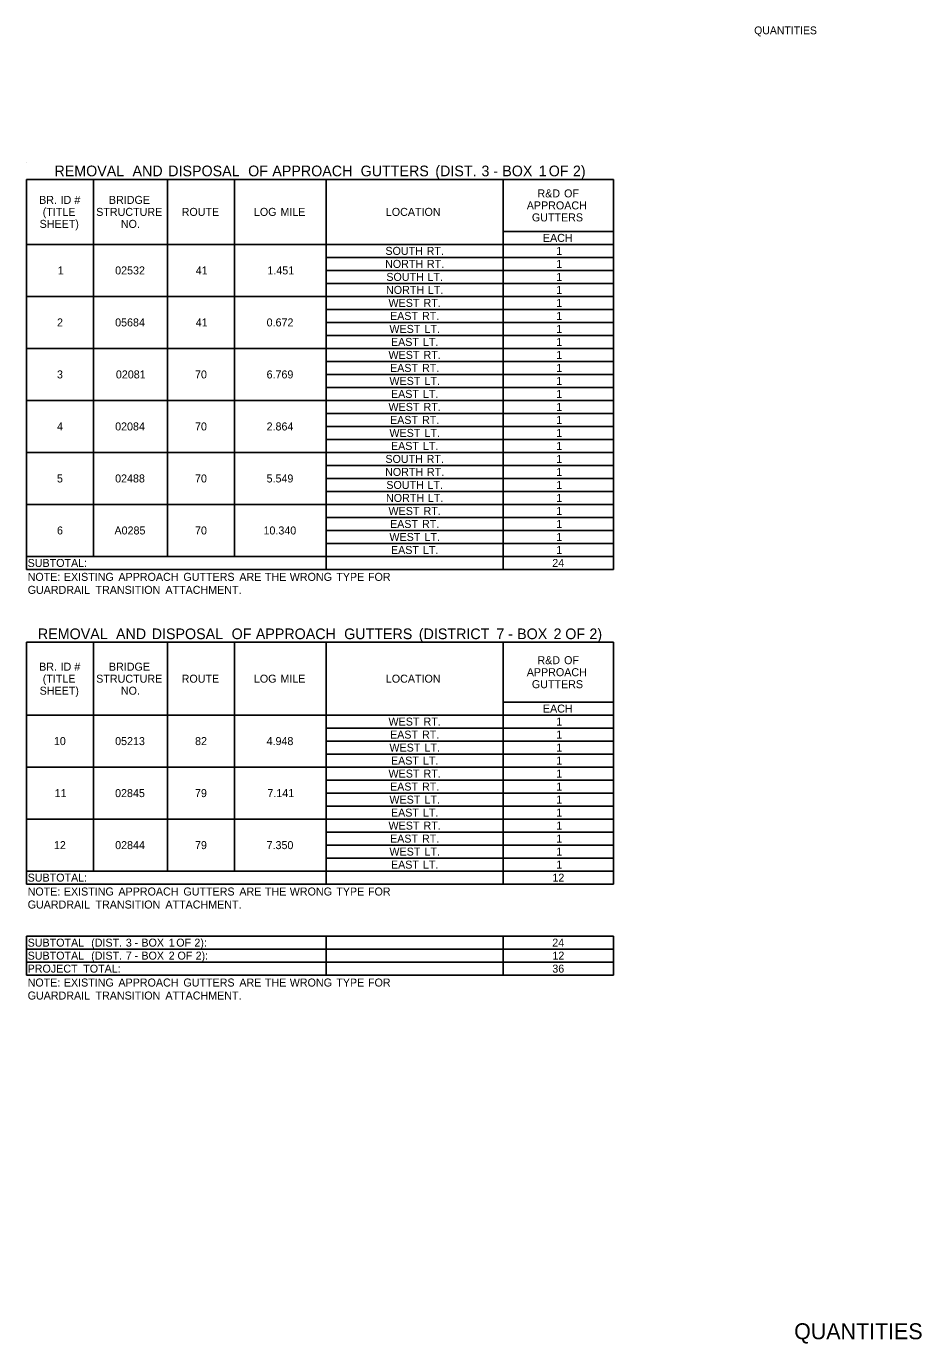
# Model space of a CAD drawing. Extents: x 544478 to 1930787, y -1948294 to 596640.
# Drawn here: x 560318 to 560989, y -1947044 to -1946056 of the extents above; entities that cross this region are included whole.
import ezdxf

# ---------------------------------------------------------------- set-up
doc = ezdxf.new("R2010")
doc.units = 0
for name, color, linetype in [('Default', 7, 'Continuous'), ('R_Border', 7, 'Continuous'), ('R_Border Prem', 7, 'Continuous')]:
    doc.layers.add(name, color=color, linetype=linetype)

msp = doc.modelspace()

# ---------------------------------------------------------------- linework, layer by layer
at = {"layer": 'Default'}
for p, q in [((560317.58, -1946158.53), (560317.58, -1946158.53)), ((560317.58, -1946171.21), (560757.79, -1946171.21)), ((560317.58, -1946463.71), (560317.58, -1946171.21)), ((560367.79, -1946453.96), (560367.79, -1946171.21)), ((560423.37, -1946453.96), (560423.37, -1946171.21)), ((560473.58, -1946453.96), (560473.58, -1946171.21)), ((560542.32, -1946463.71), (560542.32, -1946171.21)), ((560674.92, -1946463.71), (560674.92, -1946171.21)), ((560757.79, -1946463.71), (560757.79, -1946171.21)), ((560674.92, -1946210.21), (560757.79, -1946210.21)), ((560674.92, -1946210.21), (560757.79, -1946210.21)), ((560317.58, -1946219.96), (560757.79, -1946219.96)), ((560542.32, -1946229.71), (560757.79, -1946229.71)), ((560542.32, -1946239.46), (560757.79, -1946239.46)), ((560542.32, -1946249.21), (560757.79, -1946249.21)), ((560317.58, -1946258.96), (560542.32, -1946258.96)), ((560542.32, -1946258.96), (560757.79, -1946258.96)), ((560542.32, -1946268.71), (560757.79, -1946268.71)), ((560542.32, -1946278.46), (560757.79, -1946278.46)), ((560542.32, -1946288.21), (560757.79, -1946288.21)), ((560317.58, -1946297.96), (560757.79, -1946297.96)), ((560542.32, -1946297.96), (560757.79, -1946297.96)), ((560542.32, -1946307.71), (560757.79, -1946307.71)), ((560542.32, -1946317.46), (560757.79, -1946317.46)), ((560542.32, -1946327.21), (560757.79, -1946327.21)), ((560317.58, -1946336.96), (560542.32, -1946336.96)), ((560542.32, -1946336.96), (560757.79, -1946336.96)), ((560674.92, -1946336.96), (560757.79, -1946336.96)), ((560542.32, -1946346.71), (560757.79, -1946346.71)), ((560542.32, -1946356.46), (560757.79, -1946356.46)), ((560542.32, -1946366.21), (560757.79, -1946366.21)), ((560317.58, -1946375.96), (560757.79, -1946375.96)), ((560542.32, -1946375.96), (560757.79, -1946375.96)), ((560542.32, -1946385.71), (560757.79, -1946385.71)), ((560542.32, -1946395.46), (560757.79, -1946395.46)), ((560542.32, -1946405.21), (560757.79, -1946405.21)), ((560317.58, -1946414.96), (560542.32, -1946414.96)), ((560542.32, -1946414.96), (560757.79, -1946414.96)), ((560674.92, -1946414.96), (560757.79, -1946414.96)), ((560542.32, -1946424.71), (560757.79, -1946424.71)), ((560542.32, -1946434.46), (560757.79, -1946434.46)), ((560542.32, -1946444.21), (560757.79, -1946444.21)), ((560317.58, -1946453.96), (560542.32, -1946453.96)), ((560317.58, -1946453.96), (560757.79, -1946453.96)), ((560542.32, -1946463.71), (560542.32, -1946453.96)), ((560317.58, -1946463.71), (560757.79, -1946463.71)), ((560317.58, -1946518.31), (560757.79, -1946518.31)), ((560317.58, -1946699.66), (560317.58, -1946518.31)), ((560367.79, -1946689.91), (560367.79, -1946518.31)), ((560423.37, -1946689.91), (560423.37, -1946518.31)), ((560473.58, -1946689.91), (560473.58, -1946518.31)), ((560542.32, -1946699.66), (560542.32, -1946518.31)), ((560674.92, -1946699.66), (560674.92, -1946518.31)), ((560757.79, -1946699.66), (560757.79, -1946518.31)), ((560674.92, -1946563.16), (560757.79, -1946563.16)), ((560674.92, -1946563.16), (560757.79, -1946563.16)), ((560317.58, -1946572.91), (560757.79, -1946572.91)), ((560317.58, -1946572.91), (560542.32, -1946572.91)), ((560674.92, -1946572.91), (560757.79, -1946572.91)), ((560542.32, -1946582.66), (560757.79, -1946582.66)), ((560542.32, -1946592.41), (560757.79, -1946592.41)), ((560542.32, -1946602.16), (560757.79, -1946602.16)), ((560317.58, -1946611.91), (560757.79, -1946611.91)), ((560542.32, -1946611.91), (560757.79, -1946611.91)), ((560542.32, -1946621.66), (560757.79, -1946621.66)), ((560542.32, -1946631.41), (560757.79, -1946631.41)), ((560542.32, -1946641.16), (560757.79, -1946641.16)), ((560317.58, -1946650.91), (560757.79, -1946650.91)), ((560542.32, -1946650.91), (560757.79, -1946650.91)), ((560542.32, -1946660.66), (560757.79, -1946660.66)), ((560542.32, -1946670.41), (560757.79, -1946670.41)), ((560542.32, -1946680.16), (560757.79, -1946680.16)), ((560317.58, -1946689.91), (560757.79, -1946689.91)), ((560317.58, -1946689.91), (560757.79, -1946689.91)), ((560542.32, -1946699.66), (560542.32, -1946689.91)), ((560317.58, -1946699.66), (560757.79, -1946699.66)), ((560317.58, -1946738.66), (560757.79, -1946738.66)), ((560317.58, -1946738.66), (560757.79, -1946738.66)), ((560317.58, -1946767.91), (560317.58, -1946738.66)), ((560542.32, -1946767.91), (560542.32, -1946738.66)), ((560542.32, -1946767.91), (560542.32, -1946738.66)), ((560674.92, -1946767.91), (560674.92, -1946738.66)), ((560757.79, -1946767.91), (560757.79, -1946738.66)), ((560317.58, -1946748.41), (560757.79, -1946748.41)), ((560317.58, -1946758.16), (560757.79, -1946758.16)), ((560317.58, -1946767.91), (560757.79, -1946767.91))]:
    msp.add_line(p, q, dxfattribs=at)

# ---------------------------------------------------------------- texts
for s, height, p in [('REMOVAL', 8, (560338.62, -1946168.87)), (' AND', 8, (560394.18, -1946168.87)), (' DISPOSAL', 8, (560420.95, -1946168.87)), (' OF', 8, (560480.86, -1946168.87)), (' APPROACH', 8, (560498.97, -1946168.87)), (' GUTTERS', 8, (560565.19, -1946168.87)), (' (DIST.', 8, (560621.16, -1946168.87)), (' 3', 8, (560655.78, -1946168.87)), (' BOX', 8, (560671.36, -1946168.87)), (' 1', 8, (560698.68, -1946168.87)), (' OF', 8, (560706.19, -1946168.87)), (' 2)', 8, (560724.3, -1946168.87)), (' -', 8, (560664.62, -1946168.87)), ('R&D', 6, (560700.69, -1946184.71)), (' OF', 6, (560718.44, -1946184.71)), ('BR.', 6, (560327.16, -1946189.58)), ('(TITLE', 6, (560329.86, -1946198.58)), (' ID', 6, (560341.02, -1946189.58)), (' #', 6, (560351.32, -1946189.58)), ('STRUCTURE', 6, (560369.94, -1946198.58)), ('BRIDGE', 6, (560379.48, -1946189.58)), ('ROUTE', 6, (560434.01, -1946198.58)), ('LOG', 6, (560488.15, -1946198.58)), (' MILE', 6, (560505.81, -1946198.58)), ('LOCATION', 6, (560587.06, -1946198.58)), ('APPROACH', 6, (560692.69, -1946193.71)), ('SHEET)', 6, (560327.53, -1946207.58)), ('NO.', 6, (560388.42, -1946207.58)), ('GUTTERS', 6, (560696.53, -1946202.71)), ('EACH', 6, (560704.8, -1946218.08)), ('SOUTH', 6, (560586.73, -1946227.83)), (' RT.', 6, (560615.4, -1946227.83)), ('1', 6, (560714.8, -1946227.83)), ('NORTH', 6, (560586.5, -1946237.58)), (' RT.', 6, (560615.63, -1946237.58)), ('1', 6, (560714.8, -1946237.58)), ('1', 6, (560341.13, -1946242.46)), ('02532', 6, (560384.15, -1946242.46)), ('41', 6, (560444.58, -1946242.46)), ('1.451', 6, (560498.24, -1946242.46)), ('SOUTH', 6, (560587.43, -1946247.33)), (' LT.', 6, (560616.1, -1946247.33)), ('1', 6, (560714.8, -1946247.33)), ('NORTH', 6, (560587.2, -1946257.08)), (' LT.', 6, (560616.33, -1946257.08)), ('1', 6, (560714.8, -1946257.08)), ('WEST', 6, (560589.04, -1946266.83)), (' RT.', 6, (560613.09, -1946266.83)), ('1', 6, (560714.8, -1946266.83)), ('EAST', 6, (560590.2, -1946276.58)), (' RT.', 6, (560611.93, -1946276.58)), ('1', 6, (560714.8, -1946276.58)), ('2', 6, (560340.58, -1946281.46)), ('05684', 6, (560384.13, -1946281.46)), ('41', 6, (560444.58, -1946281.46)), ('0.672', 6, (560497.69, -1946281.46)), ('WEST', 6, (560589.74, -1946286.33)), (' LT.', 6, (560613.79, -1946286.33)), ('1', 6, (560714.8, -1946286.33)), ('EAST', 6, (560590.9, -1946296.08)), (' LT.', 6, (560612.63, -1946296.08)), ('1', 6, (560714.8, -1946296.08)), ('WEST', 6, (560589.04, -1946305.83)), (' RT.', 6, (560613.09, -1946305.83)), ('1', 6, (560714.8, -1946305.83)), ('EAST', 6, (560590.2, -1946315.58)), (' RT.', 6, (560611.93, -1946315.58)), ('1', 6, (560714.8, -1946315.58)), ('3', 6, (560340.55, -1946320.46)), ('02081', 6, (560384.7, -1946320.46)), ('70', 6, (560444.01, -1946320.46)), ('6.769', 6, (560497.65, -1946320.46)), ('WEST', 6, (560589.74, -1946325.33)), (' LT.', 6, (560613.79, -1946325.33)), ('1', 6, (560714.8, -1946325.33)), ('EAST', 6, (560590.9, -1946335.08)), (' LT.', 6, (560612.63, -1946335.08)), ('1', 6, (560714.8, -1946335.08)), ('WEST', 6, (560589.04, -1946344.83)), (' RT.', 6, (560613.09, -1946344.83)), ('1', 6, (560714.8, -1946344.83)), ('EAST', 6, (560590.2, -1946354.58)), (' RT.', 6, (560611.93, -1946354.58)), ('1', 6, (560714.8, -1946354.58)), ('4', 6, (560340.56, -1946359.46)), ('02084', 6, (560384.13, -1946359.46)), ('70', 6, (560444.01, -1946359.46)), ('2.864', 6, (560497.67, -1946359.46)), ('WEST', 6, (560589.74, -1946364.33)), (' LT.', 6, (560613.79, -1946364.33)), ('1', 6, (560714.8, -1946364.33)), ('EAST', 6, (560590.9, -1946374.08)), (' LT.', 6, (560612.63, -1946374.08)), ('1', 6, (560714.8, -1946374.08)), ('SOUTH', 6, (560586.73, -1946383.83)), (' RT.', 6, (560615.4, -1946383.83)), ('1', 6, (560714.8, -1946383.83)), ('NORTH', 6, (560586.5, -1946393.58)), (' RT.', 6, (560615.63, -1946393.58)), ('1', 6, (560714.8, -1946393.58)), ('5', 6, (560340.52, -1946398.46)), ('02488', 6, (560384.12, -1946398.46)), ('70', 6, (560444.01, -1946398.46)), ('5.549', 6, (560497.65, -1946398.46)), ('SOUTH', 6, (560587.43, -1946403.33)), (' LT.', 6, (560616.1, -1946403.33)), ('1', 6, (560714.8, -1946403.33)), ('NORTH', 6, (560587.2, -1946413.08)), (' LT.', 6, (560616.33, -1946413.08)), ('1', 6, (560714.8, -1946413.08)), ('WEST', 6, (560589.04, -1946422.83)), (' RT.', 6, (560613.09, -1946422.83)), ('1', 6, (560714.8, -1946422.83)), ('EAST', 6, (560590.2, -1946432.58)), (' RT.', 6, (560611.93, -1946432.58)), ('1', 6, (560714.8, -1946432.58)), ('6', 6, (560340.55, -1946437.46)), ('A0285', 6, (560383.63, -1946437.46)), ('70', 6, (560444.01, -1946437.46)), ('10.340', 6, (560495.34, -1946437.46)), ('WEST', 6, (560589.74, -1946442.33)), (' LT.', 6, (560613.79, -1946442.33)), ('1', 6, (560714.8, -1946442.33)), ('EAST', 6, (560590.9, -1946452.08)), (' LT.', 6, (560612.63, -1946452.08)), ('1', 6, (560714.8, -1946452.08)), ('SUBTOTAL:', 6, (560318.55, -1946461.83)), ('24', 6, (560711.79, -1946461.83)), ('NOTE:', 6, (560318.55, -1946472.26)), (' EXISTING', 6, (560343.44, -1946472.26)), (' APPROACH', 6, (560384.38, -1946472.26)), (' GUTTERS', 6, (560433.09, -1946472.26)), (' ARE', 6, (560475.04, -1946472.26)), (' THE', 6, (560494.16, -1946472.26)), (' WRONG', 6, (560512.8, -1946472.26)), (' TYPE', 6, (560547.67, -1946472.26)), (' FOR', 6, (560571.45, -1946472.26)), ('GUARDRAIL', 6, (560318.55, -1946482.01)), (' TRANSITION', 6, (560367.17, -1946482.01)), (' ATTACHMENT.', 6, (560419.59, -1946482.01)), ('REMOVAL', 8, (560326.24, -1946515.97)), (' AND', 8, (560381.81, -1946515.97)), (' DISPOSAL', 8, (560408.57, -1946515.97)), (' OF', 8, (560468.49, -1946515.97)), (' APPROACH', 8, (560486.6, -1946515.97)), (' GUTTERS', 8, (560552.82, -1946515.97)), (' (DISTRICT', 8, (560608.79, -1946515.97)), (' 7', 8, (560666.92, -1946515.97)), (' BOX', 8, (560682.49, -1946515.97)), (' 2', 8, (560709.81, -1946515.97)), (' OF', 8, (560718.56, -1946515.97)), (' 2)', 8, (560736.67, -1946515.97)), (' -', 8, (560675.74, -1946515.97)), ('R&D', 6, (560700.69, -1946534.73)), (' OF', 6, (560718.44, -1946534.73)), ('BR.', 6, (560327.16, -1946539.61)), (' ID', 6, (560341.02, -1946539.61)), (' #', 6, (560351.32, -1946539.61)), ('BRIDGE', 6, (560379.48, -1946539.61)), ('APPROACH', 6, (560692.69, -1946543.73)), ('(TITLE', 6, (560329.86, -1946548.61)), ('STRUCTURE', 6, (560369.94, -1946548.61)), ('ROUTE', 6, (560434.01, -1946548.61)), ('LOG', 6, (560488.15, -1946548.61)), (' MILE', 6, (560505.81, -1946548.61)), ('LOCATION', 6, (560587.06, -1946548.61)), ('GUTTERS', 6, (560696.53, -1946552.73)), ('SHEET)', 6, (560327.53, -1946557.61)), ('NO.', 6, (560388.42, -1946557.61)), ('EACH', 6, (560704.8, -1946571.03)), ('WEST', 6, (560589.04, -1946580.78)), (' RT.', 6, (560613.09, -1946580.78)), ('1', 6, (560714.8, -1946580.78)), ('EAST', 6, (560590.2, -1946590.53)), (' RT.', 6, (560611.93, -1946590.53)), ('1', 6, (560714.8, -1946590.53)), ('10', 6, (560338.23, -1946595.41)), ('05213', 6, (560384.12, -1946595.41)), ('82', 6, (560444.04, -1946595.41)), ('4.948', 6, (560497.65, -1946595.41)), ('WEST', 6, (560589.74, -1946600.28)), (' LT.', 6, (560613.79, -1946600.28)), ('1', 6, (560714.8, -1946600.28)), ('EAST', 6, (560590.9, -1946610.03)), (' LT.', 6, (560612.63, -1946610.03)), ('1', 6, (560714.8, -1946610.03)), ('WEST', 6, (560589.04, -1946619.78)), (' RT.', 6, (560613.09, -1946619.78)), ('1', 6, (560714.8, -1946619.78)), ('EAST', 6, (560590.2, -1946629.53)), (' RT.', 6, (560611.93, -1946629.53)), ('1', 6, (560714.8, -1946629.53)), ('11', 6, (560338.8, -1946634.41)), ('02845', 6, (560384.1, -1946634.41)), ('79', 6, (560444, -1946634.41)), ('7.141', 6, (560498.24, -1946634.41)), ('WEST', 6, (560589.74, -1946639.28)), (' LT.', 6, (560613.79, -1946639.28)), ('1', 6, (560714.8, -1946639.28)), ('EAST', 6, (560590.9, -1946649.03)), (' LT.', 6, (560612.63, -1946649.03)), ('1', 6, (560714.8, -1946649.03)), ('WEST', 6, (560589.04, -1946658.78)), (' RT.', 6, (560613.09, -1946658.78)), ('1', 6, (560714.8, -1946658.78)), ('EAST', 6, (560590.2, -1946668.53)), (' RT.', 6, (560611.93, -1946668.53)), ('1', 6, (560714.8, -1946668.53)), ('12', 6, (560338.25, -1946673.41)), ('02844', 6, (560384.13, -1946673.41)), ('79', 6, (560444, -1946673.41)), ('7.350', 6, (560497.67, -1946673.41)), ('WEST', 6, (560589.74, -1946678.28)), (' LT.', 6, (560613.79, -1946678.28)), ('1', 6, (560714.8, -1946678.28)), ('EAST', 6, (560590.9, -1946688.03)), (' LT.', 6, (560612.63, -1946688.03)), ('1', 6, (560714.8, -1946688.03)), ('SUBTOTAL:', 6, (560318.55, -1946697.78)), ('12', 6, (560711.91, -1946697.78)), ('NOTE:', 6, (560318.55, -1946708.21)), (' EXISTING', 6, (560343.44, -1946708.21)), (' APPROACH', 6, (560384.38, -1946708.21)), (' GUTTERS', 6, (560433.09, -1946708.21)), (' ARE', 6, (560475.04, -1946708.21)), (' THE', 6, (560494.16, -1946708.21)), (' WRONG', 6, (560512.8, -1946708.21)), (' TYPE', 6, (560547.67, -1946708.21)), (' FOR', 6, (560571.45, -1946708.21)), ('GUARDRAIL', 6, (560318.55, -1946717.96)), (' TRANSITION', 6, (560367.17, -1946717.96)), (' ATTACHMENT.', 6, (560419.59, -1946717.96)), ('SUBTOTAL', 6, (560318.55, -1946746.53)), (' (DIST.', 6, (560363.95, -1946746.53)), (' 3', 6, (560389.91, -1946746.53)), (' -', 6, (560396.54, -1946746.53)), (' BOX', 6, (560401.6, -1946746.53)), (' 1', 6, (560422.09, -1946746.53)), (' OF', 6, (560427.72, -1946746.53)), (' 2):', 6, (560441.3, -1946746.53)), ('24', 6, (560711.79, -1946746.53)), ('SUBTOTAL', 6, (560318.55, -1946756.28)), (' (DIST.', 6, (560363.95, -1946756.28)), (' 7', 6, (560389.91, -1946756.28)), (' -', 6, (560396.53, -1946756.28)), (' BOX', 6, (560401.59, -1946756.28)), (' 2', 6, (560422.08, -1946756.28)), (' OF', 6, (560428.64, -1946756.28)), (' 2):', 6, (560442.23, -1946756.28)), ('12', 6, (560711.91, -1946756.28)), ('PROJECT', 6, (560318.55, -1946766.03)), (' TOTAL:', 6, (560357.98, -1946766.03)), ('36', 6, (560711.84, -1946766.03)), ('NOTE:', 6, (560318.55, -1946776.46)), (' EXISTING', 6, (560343.44, -1946776.46)), (' APPROACH', 6, (560384.38, -1946776.46)), (' GUTTERS', 6, (560433.09, -1946776.46)), (' ARE', 6, (560475.04, -1946776.46)), (' THE', 6, (560494.16, -1946776.46)), (' WRONG', 6, (560512.8, -1946776.46)), (' TYPE', 6, (560547.67, -1946776.46)), (' FOR', 6, (560571.45, -1946776.46)), ('GUARDRAIL', 6, (560318.55, -1946786.21)), (' TRANSITION', 6, (560367.17, -1946786.21)), (' ATTACHMENT.', 6, (560419.59, -1946786.21))]:
    msp.add_text(s, height=height, dxfattribs=at).set_placement(p)
at = {"layer": 'R_Border'}
msp.add_text('QUANTITIES', height=12, rotation=360, dxfattribs=at).set_placement((560893.14, -1947040.95))
at = {"layer": 'R_Border Prem'}
msp.add_text('QUANTITIES', height=5.862, rotation=360, dxfattribs=at).set_placement((560863.16, -1946062.39))

doc.saveas('drawing.dxf')
